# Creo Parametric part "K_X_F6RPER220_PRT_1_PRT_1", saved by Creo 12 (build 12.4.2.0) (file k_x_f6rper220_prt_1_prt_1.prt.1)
Units: Custom; MM, KILOGRAM, SECS

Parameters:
  PTC_WM_ITERATION = "0"
  PTC_WM_VERSION = "-.0"
  PTC_WM_LIFECYCLE_STATE = "In Work"
  PTC_WM_LIFECYCLE = "MO_CADDocument"
  PTC_WM_CREATED_BY = "Maximilian Roepper (Z0017RMS: MO)"
  PTC_WM_CREATED_ON = "18-Sep-26 11:36:42 AM"
  PTC_WM_MODIFIED_BY = "Maximilian Roepper (Z0017RMS: MO)"
  PTC_WM_MODIFIED_ON = "18-Sep-26 11:36:46 AM"
  PDMLINKNUMBER = "PDM000071455254"
  PTC_WM_NAME = "k_x_f6rper220_prt_1_prt_1.prt"
  PTC_WM_NUMBER = "PDM000071455254"

Other parameters: WEIGHT, WEIGHT_FACTOR, WEIGHT_ADD, _MASS_TEMP, _DIFF_TEMP, MC_ERRORS, SUPPLIER

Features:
  1. coordinate system
  2. datum plane "PRT_YZ"
  3. datum plane "PRT_XY"
  4. datum plane "PRT_XZ"
  5. coordinate system
  6. datum axis
  7. datum axis
  8. datum axis
  9. coordinate system
  10. imported feature
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
Other named items: PRT, SIEMENS_MO, DRW_VIEW_ORG, PRT_X, PRT_Y, PRT_Z, CS0, ROUGH_GROB

Layers: 00_STD_CSYS-KSYS, 01_STD_PLANES-EBENEN, 02_STD_AXES-ACHSEN, 03_STD_CSYS-KSYS, 24_IMPORT_FEAT-IMPORT_KE

Surfaces: 11 tabulated cylinder, 8 plane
